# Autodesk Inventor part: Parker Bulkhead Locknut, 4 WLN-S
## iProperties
Shininess: 27.0
Category: Hydraulics
Created: 2001-03
Part Number: Parker Bulkhead Locknut, 4 WLN-S
Description: Parker Bulkhead Locknut, 4 WLN-S
Document SubType Name: Modeling
Designer: QBZ
Material: Steel, Mild
Catalog Web Link: http://www.aeroquip.com
Density: 7.860000000000001
Volumn: 2.138618301835608
Area: 16.833572068141628
PropertySet Name: Model Information
Control State: 0
Master: False
Checked Out: False
Last Check In Date: 2003-09-27
Last Check In By: Charles Bliss
Title: JIC Bulkhead Jam Nut
Author: QBZ
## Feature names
1. Extrusion1
2. Revolution1
